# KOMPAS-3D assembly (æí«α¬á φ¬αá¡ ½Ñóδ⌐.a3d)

Referenced files in D:\МОДЕЛЬ ТАНКА Т90\ДЕТАЛИ\КОРПУС\МЕТАЛЛ\КОРПУС ШТАМПОВКА\: экран левый.m3d
Referenced files in D:\МОДЕЛЬ ТАНКА Т90\ДЕТАЛИ\ОБЩИЕ ДЕТАЛИ\: шарнир экрана большой.m3d, шарниры ящиков.m3d
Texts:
  Сборка экран левый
